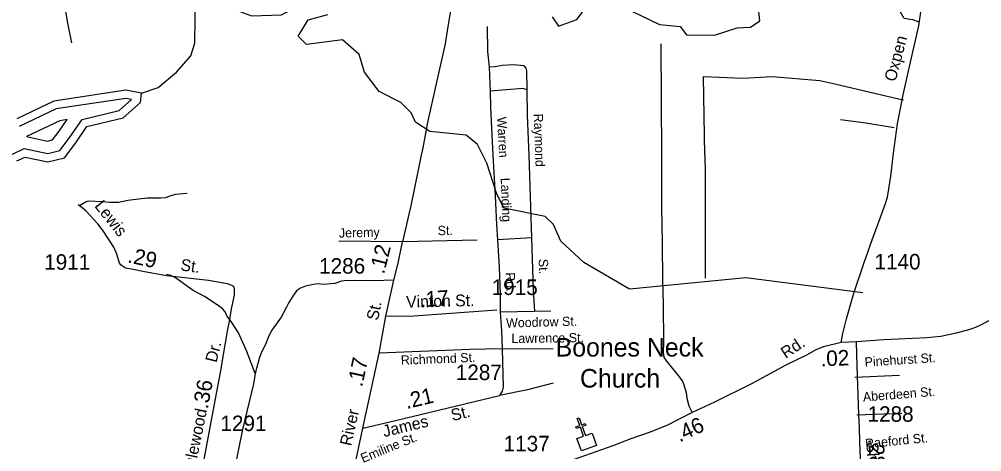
# Model space of a CAD drawing. Extents: x 2104537 to 2336408, y 34176 to 229611.
# Drawn here: x 2198609 to 2206373, y 64790 to 68278 of the extents above; entities that cross this region are included whole.
import ezdxf

# ---------------------------------------------------------------- set-up
doc = ezdxf.new("R2010")
doc.units = 0
for name, color, linetype in [('Exist Cultural Church CELL', 7, 'Continuous'), ('Exist Cultural Church Label', 7, 'Continuous'), ('Exist Hydrographic Buffer Line', 7, 'Continuous'), ('Exist Hydrographic Creek Single Shore', 7, 'Continuous'), ('Exist Hydrographic Misc Water Feature', 7, 'Continuous'), ('Exist Hydrographic River Shore', 7, 'Continuous'), ('Exist Road Non-System Type 51', 7, 'Continuous'), ('Exist Road Non-System Type 51 Label', 7, 'Continuous'), ('Exist Road Secondary Mileage Hundredths English Label', 7, 'Continuous'), ('Exist Road Secondary Type 51 Attributed', 7, 'Continuous'), ('Exist Road Secondary Type 51 Label', 7, 'Continuous'), ('Exist Road Secondary Type 51 Number Label', 7, 'Continuous')]:
    doc.layers.add(name, color=color, linetype=linetype)

msp = doc.modelspace()

# ---------------------------------------------------------------- linework, layer by layer
at = {"layer": 'Exist Cultural Church CELL'}
msp.add_lwpolyline([(2203107.3, 64896.9), (2203160.9, 64916.1), (2203135.3, 64987.8), (2203105.2, 64977.1), (2203099.8, 64992.1), (2203130, 65002.9), (2203109.7, 65059.5), (2203124.8, 65064.9), (2203145.1, 65008.3), (2203175.2, 65019), (2203180.6, 65004), (2203150.4, 64993.2), (2203176, 64921.5), (2203230.4, 64940.8), (2203266.1, 64840.5), (2203143.1, 64796.6)], close=True, dxfattribs=at)
at = {"layer": 'Exist Hydrographic Buffer Line'}
for points in [[(2198550.2, 67188), (2198648.8, 67235), (2198839.6, 67193.9), (2198935.5, 67218.1), (2199011.6, 67318.2), (2199115.8, 67470.4), (2199415.6, 67542.3), (2199514.7, 67630.4)], [(2199514.7, 67630.4), (2199469, 67638.5), (2198907, 67554.4), (2198608.9, 67412.9)], [(2198994.9, 67468), (2198936.1, 67459.2), (2198667.4, 67331.7)], [(2198667.4, 67331.7), (2198837.8, 67295), (2198878.1, 67305.1), (2198931.8, 67375.8), (2198994.9, 67468)]]:
    msp.add_lwpolyline(points, dxfattribs=at)
at = {"layer": 'Exist Hydrographic Creek Single Shore'}
for points in [[(2199594.7, 67682.9), (2199728.8, 67726.3), (2199877.9, 67851.3), (2199992.7, 67983.6), (2200025.7, 68084.7), (2200031.9, 68478.3), (2200097.7, 68526.2), (2200222.8, 68471.3), (2200331.9, 68360.9), (2200482.8, 68305.5), (2200723.7, 68314), (2200914.8, 68415.3), (2201079.9, 68599.1), (2201155.8, 68594.4)], [(2202906.9, 68298.2), (2202957.8, 68221.7), (2203106.9, 68274.6), (2203172.9, 68365.2)], [(2203556.9, 68341.4), (2203773.9, 68235.6), (2203940.8, 68219.2), (2203990.8, 68152.6), (2204216, 68148.2), (2204398.9, 68207.1), (2204508, 68214.8), (2204581.8, 68265.9), (2204573, 68367.7)]]:
    msp.add_lwpolyline(points, dxfattribs=at)
at = {"layer": 'Exist Hydrographic Misc Water Feature'}
msp.add_lwpolyline([(2205414.5, 66071), (2204470.9, 66191.3), (2203530.9, 66101.1), (2203162.8, 66315), (2202977.9, 66489.1), (2202918.8, 66621.5), (2202851.8, 66688.4), (2202517.9, 66753.9), (2202458.9, 66876.4), (2202381.8, 67117.4), (2202305.9, 67266.5), (2202213.9, 67343.7), (2201921.9, 67372.3), (2201804.8, 67446.7), (2201770.9, 67522.8), (2201686.9, 67606.5), (2201511.8, 67695.2), (2201393.9, 67851.7), (2201350.8, 67993.5), (2201216.9, 68110.9), (2200925.9, 68073.9), (2200858.9, 68140.8), (2200940.9, 68273.7), (2201098.8, 68316.6)], dxfattribs=at)
at = {"layer": 'Exist Hydrographic River Shore'}
for points in [[(2199594.7, 67682.9), (2199469.8, 67705), (2198887.7, 67617.8), (2198588.7, 67475.9)], [(2198590.8, 67134.7), (2198656.8, 67166.2), (2198840.7, 67126.6), (2198973.8, 67160.1), (2199064.9, 67279.8), (2199155.7, 67412.5), (2199446.9, 67482.3), (2199587.8, 67607.6), (2199594.7, 67682.9)]]:
    msp.add_lwpolyline(points, dxfattribs=at)
at = {"layer": 'Exist Road Non-System Type 51'}
for p, q in [((2199033.3, 68087.1), (2199006.7, 68218.9)), ((2203784.8, 68078.5), (2203789.6, 67181.6)), ((2202399, 67892.6), (2202407.7, 67696.6)), ((2205701.1, 67637.2), (2205740.4, 67628)), ((2202745.1, 66515.2), (2202721.4, 67181.2)), ((2202303.5, 66495.2), (2201701.2, 66483.5)), ((2202745.1, 66515.2), (2202467.3, 66499.6)), ((2202769.1, 65921.6), (2202489.2, 65915.8)), ((2202896.8, 65925), (2202769.1, 65921.6))]:
    msp.add_line(p, q, dxfattribs=at)
for points in [[(2202147.3, 69233.4), (2202153.7, 69191.3), (2202133.6, 68747.1), (2202121.8, 68573.1), (2202104.8, 68443.2), (2202067.5, 68218.9)], [(2199006.7, 68218.9), (2198995, 68276.4), (2198951.1, 68553.9), (2198903.8, 68805.1), (2198855.8, 69104.6)], [(2205869.1, 68253.3), (2205816, 68271.7), (2205791.8, 68276.6), (2205765.9, 68279.8), (2205746.5, 68284.7), (2205715.7, 68341.3)], [(2202067.5, 68218.9), (2202044.3, 68079.9), (2201968.7, 67745), (2201902.9, 67446.1), (2201863.5, 67241.5), (2201851, 67180.9)], [(2202384.7, 68218.9), (2202387.3, 68016.5), (2202399, 67892.6)], [(2202705.5, 67708.5), (2202703.2, 67862.4), (2202697, 67884.2), (2202683, 67902.2), (2202592.9, 67909.2), (2202504.8, 67903.7), (2202446.9, 67895.3), (2202399, 67892.6)], [(2204139.6, 67181.7), (2204128.7, 67816.9), (2204445.7, 67803.4), (2204681.7, 67816.9), (2205066.1, 67783.2), (2205187.5, 67756.2), (2205701.1, 67637.2)], [(2202705.5, 67708.5), (2202671.2, 67720), (2202407.7, 67696.6)], [(2202721.4, 67181.2), (2202710, 67500.8), (2202705.5, 67708.5)], [(2202407.7, 67696.6), (2202409.1, 67566.6), (2202430.6, 67181.1)], [(2205667.7, 67401.8), (2205437.8, 67440), (2205233.5, 67465.3)], [(2201851, 67180.9), (2201769.4, 66786.3), (2201701.2, 66483.5)], [(2202430.6, 67181.1), (2202448.8, 66853.3), (2202457.5, 66623.4), (2202467.3, 66499.6)], [(2203789.6, 67181.6), (2203790.1, 67078.7), (2203788.4, 66754.6), (2203796, 66480.8), (2203798.1, 66166.8), (2203802.5, 65984.7), (2203806.6, 65669), (2203803.5, 65595.9), (2203805.9, 65566.9), (2203810.2, 65548.8), (2203830.3, 65519.6), (2203934.4, 65390.6), (2203958, 65356), (2203966.2, 65339.1), (2203987.5, 65269.2), (2203994.5, 65221.5), (2204011.3, 65161.7), (2204036.2, 65105.8)], [(2204139.6, 67181.7), (2204142.2, 67027.6), (2204142.2, 66191.1)], [(2199963.7, 66872.9), (2199869.7, 66863.9), (2199839.7, 66857.3), (2199786.2, 66838.6), (2199750, 66834.4), (2199644, 66834.8), (2199594.4, 66830.2), (2199486.5, 66816.8), (2199410.8, 66801.2), (2199336.6, 66801), (2199280.3, 66806.1), (2199166.2, 66810.6), (2199150.4, 66804.6), (2199096.6, 66771.9)], [(2201701.2, 66483.5), (2201187.9, 66488.9)], [(2202467.3, 66499.6), (2202480.4, 66277.8), (2202489.3, 66059.8), (2202489.2, 65915.8)], [(2202769.1, 65921.6), (2202756.7, 66095), (2202745.1, 66515.2)], [(2200317.4, 65841.2), (2200284.9, 65887.1), (2200270.4, 65919.2), (2200252.1, 65938.9), (2200221.7, 65964.4), (2200104.8, 66042.8), (2200011.9, 66089.5), (2199868.8, 66191.7), (2199831.3, 66210.9), (2199798.4, 66219.3)], [(2201631.3, 66174.8), (2201473.4, 66168.6), (2201321.2, 66170.6), (2201229.9, 66169.1), (2201209.5, 66165.2), (2201155.4, 66146.9), (2201061.7, 66139.2), (2201021.4, 66142.9), (2200981.7, 66140.1), (2200917.8, 66125.6), (2200877.1, 66110.3), (2200845.2, 66086.6), (2200811, 66036.1), (2200783.7, 65993.6), (2200765.9, 65955.6), (2200721, 65876.7), (2200695.7, 65836.5), (2200647.5, 65771.2), (2200623.3, 65723.7), (2200592, 65649.2), (2200562.7, 65592.7), (2200543.3, 65542.5), (2200511.1, 65420.1)], [(2202489.2, 65915.8), (2202499, 65764), (2202504.8, 65619.9)], [(2200511.1, 65420.1), (2200445.4, 65599.6), (2200377.3, 65750), (2200317.4, 65841.2)], [(2202504.8, 65619.9), (2202247.1, 65614.7), (2201511.3, 65585.2)], [(2202504.8, 65619.9), (2202513.2, 65310), (2202503.4, 65278.1), (2202481.8, 65243.7)], [(2202917.2, 65621.1), (2202679, 65618.2), (2202504.8, 65619.9)], [(2200511.1, 65420.1), (2200498.1, 65338), (2200408.9, 64968.7), (2200343.2, 64640.2), (2200321.2, 64487.8), (2200306.4, 64315.5), (2200304.3, 64257.8), (2200298.5, 64245.4), (2200263.1, 64196.9)], [(2205348.4, 65392.1), (2205709.7, 65408.2)], [(2202916.8, 65343.3), (2202709.4, 65290.8), (2202481.8, 65243.7)], [(2205365.6, 65089), (2205727.9, 65102.6)]]:
    msp.add_lwpolyline(points, dxfattribs=at)
at = {"layer": 'Exist Road Secondary Type 51 Attributed'}
for points in [[(2205238.5, 65671), (2205252.2, 65743.2), (2205281.4, 65862.2), (2205341.9, 66069.1), (2205421.9, 66309.1), (2205490.2, 66498.4), (2205554.5, 66674.1), (2205597.4, 66791.1), (2205613, 66843.8), (2205624.7, 66910.2), (2205638.4, 67013.6), (2205659.9, 67197), (2205693, 67435.1), (2205737.9, 67669.3), (2205798.3, 67932.7), (2205864.7, 68223.5), (2205884.1, 68353)], [(2200340.4, 66118.7), (2200323.4, 66130), (2200289.3, 66144.2), (2200136.1, 66169.8), (2199800, 66210), (2199619.1, 66240.4), (2199516, 66262.3), (2199465.9, 66271.1), (2199440.9, 66287.9), (2199428.4, 66297.3), (2199418.4, 66309.8), (2199395.9, 66382.4), (2199372.2, 66439.9), (2199286.1, 66571.6), (2199244.3, 66628.2), (2199148.3, 66729.1), (2199113.9, 66758.6), (2199083.4, 66780.1)], [(2201567.3, 65883.2), (2201631.3, 66174.8), (2201665.8, 66311.3), (2201701.2, 66483.5)], [(2200010.2, 64265.8), (2200053.4, 64470.5), (2200192.9, 65216.5), (2200232.6, 65429.3), (2200267.3, 65636.7), (2200289.4, 65762.2), (2200306.7, 65855.7), (2200321.4, 65941.8), (2200346.1, 66053.4), (2200346.1, 66104.5), (2200340.4, 66118.7)], [(2201567.3, 65883.2), (2201792.3, 65886.8), (2202462.7, 65933.9)], [(2201382, 64981.6), (2201511.3, 65585.2), (2201567.3, 65883.2)], [(2206504.6, 65886.7), (2206363.4, 65811), (2206323.7, 65792.7), (2206276.8, 65775.9), (2206167, 65745.2), (2206044.1, 65719.8), (2205929.6, 65707.8), (2205582.6, 65692.8), (2205362.3, 65677.3)], [(2205238.5, 65671), (2205097.3, 65637.5), (2205033.8, 65612.8), (2204964.5, 65571.9), (2204793.2, 65487.9), (2204515.1, 65338.1), (2204211, 65186.1), (2204036.2, 65105.8), (2203833.4, 65003.1), (2203690.3, 64945.5), (2203543, 64895.5), (2203397.5, 64837.6), (2203030.8, 64707.7)], [(2205362.3, 65677.3), (2205238.5, 65671)], [(2205419.3, 64196), (2205405.6, 64609.7), (2205392, 64785.4), (2205386.1, 64980.5), (2205380.3, 65091.7), (2205368.6, 65480.1), (2205362.3, 65677.3)], [(2201382, 64981.6), (2201644.3, 65042.7), (2202481.8, 65243.7)], [(2201228.7, 64265.6), (2201266, 64448.2), (2201304, 64614.5), (2201382, 64981.6)]]:
    msp.add_lwpolyline(points, dxfattribs=at)

# ---------------------------------------------------------------- texts
at = {"layer": 'Exist Cultural Church Label'}
for s, p in [('Boones Neck', (2202935.9, 65558)), ('Church', (2203132.2, 65307.5))]:
    msp.add_text(s, height=150, dxfattribs=at).set_placement(p)
at = {"layer": 'Exist Road Non-System Type 51 Label'}
for s, rotation, p in [('Warren', 273.18751, (2202462.7, 67488.4)), ('Raymond', 272.04165, (2202758.7, 67515.3)), ('Landing', 272.16644, (2202492.6, 66998)), ('St.', 1.39001, (2201985.1, 66535.9)), ('Jeremy', 1.39001, (2201188.8, 66516.6)), ('St.', 271.57933, (2202799.1, 66344.5)), ('Rd.', 272.34305, (2202531.4, 66235.6)), ('Woodrow St.', 1.54538, (2202536.9, 65791)), ('Lawrence St.', 0.71008, (2202579.5, 65666.2)), ('Richmond St.', 2.29244, (2201688.6, 65491.2)), ('Pinehurst St.', 3.67804, (2205430.4, 65476.1)), ('Aberdeen St.', 4.57837, (2205417, 65194.3)), ('Emiline St.', 22.20873, (2201381.8, 64699.5)), ('Raeford St.', 5.63841, (2205436.5, 64817.8))]:
    msp.add_text(s, height=75, rotation=rotation, dxfattribs=at).set_placement(p)
at = {"layer": 'Exist Road Secondary Mileage Hundredths English Label'}
for s, rotation, p in [('.12', 75.83065, (2201551.5, 66217.4)), ('.29', 348.01888, (2199477.6, 66317.7)), ('.17', 4.02538, (2201846, 65954.1)), ('.02', 2.17684, (2205074.4, 65478.6)), ('.17', 77.90908, (2201375.2, 65307.4)), ('.36', 79.42643, (2200129.6, 65130.1)), ('.21', 13.49852, (2201734.5, 65134)), ('.46', 24.67434, (2203935, 64865.3)), ('.28', 273.0113, (2205457.7, 64895.5))]:
    msp.add_text(s, height=125, rotation=rotation, dxfattribs=at).set_placement(p)
at = {"layer": 'Exist Road Secondary Type 51 Label'}
for s, rotation, p in [('Oxpen', 75.21632, (2205677.1, 67769.1)), ('Lewis', 308.35651, (2199211.6, 66770.6)), ('St.', 351.65256, (2199905.8, 66253.3)), ('Vinton St.', 1.45799, (2201731.1, 65951.5)), ('St.', 78.35246, (2201502.3, 65843.4)), ('Rd.', 33.39521, (2204791.7, 65537.6)), ('Dr.', 76.26628, (2200200.3, 65504.3)), ('Tanglewood ', 78.55089, (2199987.4, 64449.6)), ('St.', 13.4985, (2202103.9, 65037)), ('River', 77.33705, (2201286.5, 64831.8)), ('James', 13.4985, (2201552.6, 64907.5)), ('Shoreline', 273.37174, (2205442.5, 64863.3))]:
    msp.add_text(s, height=95, rotation=rotation, dxfattribs=at).set_placement(p)
at = {"layer": 'Exist Road Secondary Type 51 Number Label'}
for s, p in [('1911', (2198810.4, 66257.7)), ('1140', (2205507.5, 66260.3)), ('1286', (2201027.9, 66226.4)), ('1915', (2202419.5, 66054.2)), ('1287', (2202130.3, 65368.3)), ('1288', (2205451.5, 65031.8)), ('1291', (2200231.7, 64956.7)), ('1137', (2202516, 64793.6))]:
    msp.add_text(s, height=125, dxfattribs=at).set_placement(p)

doc.saveas('drawing.dxf')
